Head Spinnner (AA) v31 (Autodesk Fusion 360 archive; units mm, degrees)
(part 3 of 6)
sketch "Switch Housing Clearance" plane through (0, 0, -2.54) normal (0, 0, -1) x axis (1, 0, 0)
  line L1 (-21.6642, -66.6778) -> (23.0262, -66.6778)
  line L2 (-30.1868, -67.591) -> (-21.6642, -66.6778)
  line L3 (-30.1868, -39.2217) -> (-30.1868, -67.591)
  line L4 (-21.6642, -40.1348) -> (-30.1868, -39.2217)
  line L5 (23.0262, -40.1348) -> (-21.6642, -40.1348)
  line L6 (23.0262, -66.6778) -> (23.0262, -40.1348)
  line L7 (-11.2776, 70.5993) -> (-11.2776, 56.4007)
  line L8 (10.5219, 71.0121) -> (-10.522, 71.0121)
  line L9 (11.2776, 56.4007) -> (11.2776, 70.5993)
  line L10 (-10.522, 55.988) -> (10.5219, 55.988)
  line L11 (-11.2776, 55.988) -> (-10.522, 55.988)
  line L12 (-11.2776, 55.988) -> (-11.2776, 56.4007)
  line L13 (11.2776, 71.0121) -> (11.2776, 70.5993)
  line L14 (11.2776, 71.0121) -> (10.5219, 71.0121)
  line L15 (11.2776, 55.988) -> (-11.2776, 55.988)
  line L16 (11.2776, 71.0121) -> (11.2776, 55.988)
  line L17 (-11.2776, 71.0121) -> (11.2776, 71.0121)
  line L18 (-11.2776, 55.988) -> (-11.2776, 71.0121)
  line L19 (-11.5316, 71.2661) -> (11.5316, 71.2661)
  line L20 (-11.5316, 55.734) -> (-11.5316, 71.2661)
  line L21 (11.5316, 55.734) -> (-11.5316, 55.734)
  line L22 (11.5316, 71.2661) -> (11.5316, 55.734)
  circle C1 centre (0, -84.1375) radius 3.328
  circle C2 centre (82.028, 18.7224) radius 3.328
  circle C3 centre (-36.5059, 75.8053) radius 3.328
  circle C4 centre (-65.7813, -52.4589) radius 3.328
  circle C5 centre (0, 0) radius 88.9
  circle C6 centre (-82.028, 18.7224) radius 3.328
  circle C7 centre (36.5059, 75.8053) radius 3.328
  circle C8 centre (65.7813, -52.4589) radius 3.328
  point P23 (-10.522, 55.988)
  point P24 (-10.522, 55.988)
  point P16 (-11.2776, 56.4007)
  point P25 (-11.2776, 56.4007)
  point P20 (11.2776, 70.5993)
  point P27 (11.2776, 70.5993)
  point P19 (10.5219, 71.0121)
  point P28 (10.5219, 71.0121)
  coincident P23 P24
  parallel L10 L11
  coincident P16 P25
  vertical L12
  coincident P20 P27
  parallel L9 L13
  coincident P19 P28
  perpendicular L13 L14
  horizontal L15
  vertical L16
  horizontal L17
  vertical L18
extrude "Extrude20" cut sketch "Switch Housing Clearance" profile of L20 L19 L21 L22 against normal blind 5.715
offset_faces "OffsetFaces3" distance 0.0318
extrude "Extrude30" add of existing geometry blind 0.2794
extrude "Extrude31" add of existing geometry blind 0.3048
fillet "Fillet4" radius 0.635
chamfer "Chamfer6" distance 1.27
sketch "Battery Cover Profile" plane through (0, 0, -2.54) normal (0, 0, -1) x axis (1, 0, 0)
  line L1 (11.2268, 71.2661) -> (-11.2522, 71.2661)
  line L2 (-11.2522, 55.734) -> (11.2268, 55.734)
  line L3 (-21.6642, -66.6778) -> (23.0262, -66.6778)
  line L4 (-30.1868, -67.591) -> (-21.6642, -66.6778)
  line L5 (-30.1868, -39.2217) -> (-30.1868, -67.591)
  line L6 (-21.6642, -40.1348) -> (-30.1868, -39.2217)
  line L7 (23.0262, -40.1348) -> (-21.6642, -40.1348)
  line L8 (23.0262, -66.6778) -> (23.0262, -40.1348)
  line L9 (-21.5285, -69.2178) -> (25.5662, -69.2178)
  line L10 (-32.7268, -70.4176) -> (-21.5285, -69.2178)
  line L11 (-32.7268, -36.395) -> (-32.7268, -70.4176)
  line L12 (-21.5285, -37.5948) -> (-32.7268, -36.395)
  line L13 (25.5662, -37.5948) -> (-21.5285, -37.5948)
  line L14 (25.5662, -69.2178) -> (25.5662, -37.5948)
  line L15 (-39.0768, -47.6913) -> (-32.7268, -47.6913)
  line L16 (-39.0768, -59.1213) -> (-39.0768, -47.6913)
  line L17 (-32.7268, -59.1213) -> (-39.0768, -59.1213)
  line L18 (-32.7268, -53.4063) -> (-39.0768, -53.4063)
  line L19 (25.5662, -53.4063) -> (-32.7268, -53.4063)
  line L20 (-3.5803, -33.02) -> (-3.5803, -53.4063)
  line L21 (31.9162, -47.6913) -> (25.5662, -47.6913)
  line L22 (25.5662, -59.1213) -> (31.9162, -59.1213)
  line L23 (11.2268, 55.734) -> (11.2268, 71.2661)
  line L24 (-11.2522, 71.2661) -> (-11.2522, 55.734)
  circle C1 centre (0, -84.1375) radius 3.328
  circle C2 centre (82.028, 18.7224) radius 3.328
  circle C3 centre (-36.5059, 75.8053) radius 3.328
  circle C4 centre (-65.7813, -52.4589) radius 3.328
  circle C5 centre (0, 0) radius 88.9
  circle C6 centre (-82.028, 18.7224) radius 3.328
  circle C7 centre (36.5059, 75.8053) radius 3.328
  circle C8 centre (65.7813, -52.4589) radius 3.328
  arc A1 centre (-39.0768, -53.4063) radius 5.715 clockwise from (-39.0768, -59.1213) to (-39.0768, -47.6913)
  arc A2 centre (31.9162, -53.4063) radius 5.715 clockwise from (31.9162, -47.6913) to (31.9162, -59.1213)
  point P26 (-32.7268, -47.6913)
  point P29 (-32.7268, -59.1213)
  point P31 (-39.0768, -53.4063)
  point P32 (-32.7268, -53.4063)
  point P33 (25.5662, -53.4063)
  point P34 (-3.5803, -53.4063)
  point P36 (25.5662, -47.6913)
  point P27 (-39.0768, -47.6913)
  point P37 (31.9162, -47.6913)
  point P28 (-39.0768, -59.1213)
  point P38 (31.9162, -59.1213)
  point P39 (25.5662, -59.1213)
  coincident L11 P26
  perpendicular L11 L15
  perpendicular L15 L16
  coincident L11 P29
  horizontal L17
  midpoint L16 P31
  midpoint L11 P32
  horizontal L18
  tangent L17 A1
  midpoint L14 P33
  midpoint L19 P34
  perpendicular L13 L20
  symmetric P26 L20 P36
  symmetric P27 L20 P37
  symmetric P28 L20 P38
  symmetric P29 L20 P39
  symmetric A1 L20 A2
  dimension "d240" = -2.54
  dimension "d241" distance P27 P28 = 11.43
  dimension "d242" distance P26 P27 = 6.35
extrude "Extrude23" cut sketch "Battery Cover Profile" profile of L3 L4 L5 L6 L7 L8 L14 L12 L10 L11 L13 L9 L15 L17 A1 L21 L22 A2 against normal blind 1.905
extrude "Extrude24" sketch "Battery Cover Profile" profile of L14 L11 L15 L17 A1 L21 L22 A2 blind -5.08
fillet "Fillet5" radius 1.27
sketch "Battery Cover Clearance" plane through (0, 0, -0.635) normal (0, 0, -1) x axis (1, 0, 0)
  line L1 (-32.7268, -46.4213) -> (-32.7268, -37.8084)
  line L2 (-39.0768, -47.6913) -> (-33.9968, -47.6913)
  line L3 (-33.9968, -59.1213) -> (-39.0768, -59.1213)
  line L4 (-32.7268, -69.0043) -> (-32.7268, -60.3913)
  line L5 (-21.596, -69.2251) -> (-31.3215, -70.2671)
  line L6 (24.2962, -69.2178) -> (-21.4607, -69.2178)
  line L7 (25.5662, -60.3913) -> (25.5662, -67.9478)
  line L8 (31.9162, -59.1213) -> (26.8362, -59.1213)
  line L9 (26.8362, -47.6913) -> (31.9162, -47.6913)
  line L10 (25.5662, -38.8648) -> (25.5662, -46.4213)
  line L11 (-21.4607, -37.5948) -> (24.2962, -37.5948)
  line L12 (-31.3215, -36.5456) -> (-21.596, -37.5876)
  line L13 (23.0262, -40.1348) -> (-21.6642, -40.1348)
  line L14 (23.0262, -66.6778) -> (23.0262, -40.1348)
  line L15 (-21.6642, -66.6778) -> (23.0262, -66.6778)
  line L16 (-30.1868, -67.591) -> (-21.6642, -66.6778)
  line L17 (-30.1868, -39.2217) -> (-30.1868, -67.591)
  line L18 (-21.6642, -40.1348) -> (-30.1868, -39.2217)
  line L19 (26.8362, -48.0723) -> (31.9162, -48.0723)
  line L20 (31.9162, -58.7403) -> (26.8362, -58.7403)
  line L21 (25.1852, -60.3913) -> (25.1852, -67.9478)
  line L22 (24.2962, -68.8368) -> (-21.4607, -68.8368)
  line L23 (-21.6366, -68.8462) -> (-31.3621, -69.8882)
  line L24 (-32.3458, -69.0043) -> (-32.3458, -60.3913)
  line L25 (-33.9968, -58.7403) -> (-39.0768, -58.7403)
  line L26 (-39.0768, -48.0723) -> (-33.9968, -48.0723)
  line L27 (-32.3458, -46.4213) -> (-32.3458, -37.8084)
  line L28 (-31.3621, -36.9244) -> (-21.6366, -37.9664)
  line L29 (-21.4607, -37.9758) -> (24.2962, -37.9758)
  line L30 (25.1852, -38.8648) -> (25.1852, -46.4213)
  arc A1 centre (-31.4568, -37.8084) radius 1.27 clockwise from (-32.7268, -37.8084) to (-31.3215, -36.5456)
  arc A2 centre (-33.9968, -46.4213) radius 1.27 clockwise from (-32.7268, -46.4213) to (-33.9968, -47.6913)
  arc A3 centre (-39.0768, -53.4063) radius 5.715 clockwise from (-39.0768, -59.1213) to (-39.0768, -47.6913)
  arc A4 centre (-33.9968, -60.3913) radius 1.27 clockwise from (-33.9968, -59.1213) to (-32.7268, -60.3913)
  arc A5 centre (-31.4568, -69.0043) radius 1.27 clockwise from (-31.3215, -70.2671) to (-32.7268, -69.0043)
  arc A6 centre (-21.4607, -70.4878) radius 1.27 clockwise from (-21.596, -69.2251) to (-21.4607, -69.2178)
  arc A7 centre (24.2962, -67.9478) radius 1.27 clockwise from (25.5662, -67.9478) to (24.2962, -69.2178)
  arc A8 centre (26.8362, -60.3913) radius 1.27 clockwise from (25.5662, -60.3913) to (26.8362, -59.1213)
  arc A9 centre (31.9162, -53.4063) radius 5.715 clockwise from (31.9162, -47.6913) to (31.9162, -59.1213)
  arc A10 centre (26.8362, -46.4213) radius 1.27 clockwise from (26.8362, -47.6913) to (25.5662, -46.4213)
  arc A11 centre (24.2962, -38.8648) radius 1.27 clockwise from (24.2962, -37.5948) to (25.5662, -38.8648)
  arc A12 centre (-21.4607, -36.3248) radius 1.27 clockwise from (-21.4607, -37.5948) to (-21.596, -37.5876)
  arc A13 centre (26.8362, -46.4213) radius 1.651 clockwise from (26.8362, -48.0723) to (25.1852, -46.4213)
  arc A14 centre (31.9162, -53.4063) radius 5.334 clockwise from (31.9162, -48.0723) to (31.9162, -58.7403)
  arc A15 centre (26.8362, -60.3913) radius 1.651 clockwise from (25.1852, -60.3913) to (26.8362, -58.7403)
  arc A16 centre (24.2962, -67.9478) radius 0.889 clockwise from (25.1852, -67.9478) to (24.2962, -68.8368)
  arc A17 centre (-21.4607, -70.4878) radius 1.651 clockwise from (-21.6366, -68.8462) to (-21.4607, -68.8368)
  arc A18 centre (-31.4568, -69.0043) radius 0.889 clockwise from (-31.3621, -69.8882) to (-32.3458, -69.0043)
  arc A19 centre (-33.9968, -60.3913) radius 1.651 clockwise from (-33.9968, -58.7403) to (-32.3458, -60.3913)
  arc A20 centre (-39.0768, -53.4063) radius 5.334 clockwise from (-39.0768, -58.7403) to (-39.0768, -48.0723)
  arc A21 centre (-33.9968, -46.4213) radius 1.651 clockwise from (-32.3458, -46.4213) to (-33.9968, -48.0723)
  arc A22 centre (-31.4568, -37.8084) radius 0.889 clockwise from (-32.3458, -37.8084) to (-31.3621, -36.9244)
  arc A23 centre (-21.4607, -36.3248) radius 1.651 clockwise from (-21.4607, -37.9758) to (-21.6366, -37.9664)
  arc A24 centre (24.2962, -38.8648) radius 0.889 clockwise from (24.2962, -37.9758) to (25.1852, -38.8648)
  dimension "d430" = -0.381 (= "-clearance * 1.5")
sketch "Motor Control Text" plane through (0, 0, -2.54) normal (0, 0, -1) x axis (1, 0, 0)
  line L1 (11.2268, 71.2661) -> (-11.2522, 71.2661)
  line L2 (11.2268, 55.734) -> (11.2268, 71.2661)
  line L3 (-11.2522, 55.734) -> (11.2268, 55.734)
  line L4 (-11.2522, 71.2661) -> (-11.2522, 55.734)
  line L5 (24.2962, -37.5948) -> (-21.4607, -37.5948)
  line L6 (25.5662, -46.4213) -> (25.5662, -38.8648)
  line L7 (31.9162, -47.6913) -> (26.8362, -47.6913)
  line L8 (26.8362, -59.1213) -> (31.9162, -59.1213)
  line L9 (25.5662, -67.9478) -> (25.5662, -60.3913)
  line L10 (-21.4607, -69.2178) -> (24.2962, -69.2178)
  line L11 (-31.3215, -70.2671) -> (-21.596, -69.2251)
  line L12 (-32.7268, -60.3913) -> (-32.7268, -69.0043)
  line L13 (-39.0768, -59.1213) -> (-33.9968, -59.1213)
  line L14 (-33.9968, -47.6913) -> (-39.0768, -47.6913)
  line L15 (-32.7268, -37.8084) -> (-32.7268, -46.4213)
  line L16 (-21.596, -37.5876) -> (-31.3215, -36.5456)
  curve K1
  curve K2
  curve K3
  curve K4
  curve K5
  curve K6
  curve K7
  curve K8
  line L17 (20.545, 64.2667) -> (20.545, 63.1491)
  line L18 (23.9552, 60.6091) -> (23.389, 60.6091)
  line L19 (22.8228, 60.6091) -> (20.545, 60.6091)
  line L20 (20.545, 63.1491) -> (20.545, 60.6091)
  line L21 (24.6329, 59.4026) -> (23.9552, 60.6091)
  line L22 (22.8228, 60.6091) -> (22.1452, 59.4026)
  line L23 (23.389, 59.4026) -> (23.389, 60.6091)
  line L24 (23.389, 61.6172) -> (22.8228, 60.6091)
  line L25 (23.9552, 60.6091) -> (23.389, 61.6172)
  line L26 (23.389, 60.6091) -> (22.8228, 60.6091)
  line L27 (23.9979, 59.4026) -> (24.6329, 59.4026)
  line L28 (22.1452, 59.4026) -> (22.7802, 59.4026)
  line L29 (22.7802, 59.4026) -> (23.9979, 59.4026)
  line L30 (-0.0127, 48.26) -> (-0.0127, 55.734)
  line L31 (-20.5704, 64.2667) -> (-20.5704, 63.1491)
  line L32 (-24.6583, 59.4026) -> (-23.9806, 60.6091)
  line L33 (-24.0233, 59.4026) -> (-24.6583, 59.4026)
  line L34 (-22.1706, 59.4026) -> (-22.8056, 59.4026)
  line L35 (-22.8482, 60.6091) -> (-22.1706, 59.4026)
  line L36 (-23.4144, 61.6172) -> (-22.8482, 60.6091)
  line L37 (-23.9806, 60.6091) -> (-23.4144, 61.6172)
  line L38 (-17.7927, 76.7271) -> (17.7673, 76.7271)
  line L39 (17.7546, 63.5) -> (-17.78, 63.5)
  line L40 (30.2768, 63.5) -> (-30.3022, 63.5)
  line L41 (-0.0127, 55.734) -> (-0.0127, 63.5)
  line L42 (17.7673, 52.559) -> (-17.7927, 52.559)
  line L43 (-17.7927, 76.8541) -> (17.7673, 76.8541)
  line L44 (17.7673, 52.432) -> (-17.7927, 52.432)
  circle C1 centre (65.7813, -52.4589) radius 3.328
  circle C2 centre (36.5059, 75.8053) radius 3.328
  circle C3 centre (-82.028, 18.7224) radius 3.328
  circle C4 centre (0, 0) radius 88.9
  circle C5 centre (-65.7813, -52.4589) radius 3.328
  circle C6 centre (-36.5059, 75.8053) radius 3.328
  circle C7 centre (82.028, 18.7224) radius 3.328
  circle C8 centre (0, -84.1375) radius 3.328
  arc A1 centre (-21.4607, -36.3248) radius 1.27 clockwise from (-21.4607, -37.5948) to (-21.596, -37.5876)
  arc A2 centre (24.2962, -38.8648) radius 1.27 clockwise from (24.2962, -37.5948) to (25.5662, -38.8648)
  arc A3 centre (26.8362, -46.4213) radius 1.27 clockwise from (26.8362, -47.6913) to (25.5662, -46.4213)
  arc A4 centre (31.9162, -53.4063) radius 5.715 clockwise from (31.9162, -47.6913) to (31.9162, -59.1213)
  arc A5 centre (26.8362, -60.3913) radius 1.27 clockwise from (25.5662, -60.3913) to (26.8362, -59.1213)
  arc A6 centre (24.2962, -67.9478) radius 1.27 clockwise from (25.5662, -67.9478) to (24.2962, -69.2178)
  arc A7 centre (-21.4607, -70.4878) radius 1.27 clockwise from (-21.596, -69.2251) to (-21.4607, -69.2178)
  arc A8 centre (-31.4568, -69.0043) radius 1.27 clockwise from (-31.3215, -70.2671) to (-32.7268, -69.0043)
  arc A9 centre (-33.9968, -60.3913) radius 1.27 clockwise from (-33.9968, -59.1213) to (-32.7268, -60.3913)
  arc A10 centre (-39.0768, -53.4063) radius 5.715 clockwise from (-39.0768, -59.1213) to (-39.0768, -47.6913)
  arc A11 centre (-33.9968, -46.4213) radius 1.27 clockwise from (-32.7268, -46.4213) to (-33.9968, -47.6913)
  arc A12 centre (-31.4568, -37.8084) radius 1.27 clockwise from (-32.7268, -37.8084) to (-31.3215, -36.5456)
  arc A13 centre (20.545, 60.6091) radius 2.54 clockwise from (22.7802, 59.4026) to (20.545, 63.1491)
  arc A14 centre (20.545, 60.6091) radius 3.6576 clockwise from (23.9979, 59.4026) to (20.545, 64.2667)
  arc A15 centre (-20.5704, 60.6091) radius 3.6576 clockwise from (-20.5704, 64.2667) to (-24.0233, 59.4026)
  arc A16 centre (-20.5704, 60.6091) radius 2.54 clockwise from (-20.5704, 63.1491) to (-22.8056, 59.4026)
  arc A17 centre (-17.7927, 64.643) radius 12.0841 clockwise from (-17.7927, 52.559) to (-17.7927, 76.7271)
  arc A18 centre (17.7673, 64.643) radius 12.0841 clockwise from (17.7673, 76.7271) to (17.7673, 52.559)
  arc A19 centre (17.7673, 64.643) radius 12.2111 clockwise from (17.7673, 76.8541) to (17.7673, 52.432)
  arc A20 centre (-17.7927, 64.643) radius 12.2111 clockwise from (-17.7927, 52.432) to (-17.7927, 76.8541)
  point P12 (11.2268, 55.734)
  point P10 (-11.2522, 71.2661)
  point P50 (20.545, 60.6091)
  point P52 (20.545, 60.6091)
  point P62 (22.7802, 59.4026)
  point P60 (23.389, 59.4026)
  point P51 (20.545, 60.6091)
  point P64 (23.389, 59.4026)
  point P65 (-0.0127, 55.734)
  point P53 (20.545, 64.2667)
  point P68 (-20.5704, 64.2667)
  point P54 (23.9552, 60.6091)
  point P73 (-23.9806, 60.6091)
  point P55 (22.8228, 60.6091)
  point P76 (-22.8482, 60.6091)
  point P56 (20.545, 63.1491)
  point P71 (-20.5704, 63.1491)
  point P57 (24.6329, 59.4026)
  point P74 (-24.6583, 59.4026)
  point P58 (22.1452, 59.4026)
  point P75 (-22.1706, 59.4026)
  point P61 (23.389, 61.6172)
  point P77 (-23.4144, 61.6172)
  point P72 (-22.8056, 59.4026)
  point P63 (23.9979, 59.4026)
  point P69 (-24.0233, 59.4026)
  point P84 (-0.0127, 63.5)
  point P85 (-30.3022, 63.5)
  point P86 (30.2768, 63.5)
  point P87 (-0.0127, 63.5)
  point P88 (-0.0127, 63.5)
  point P13 (-11.2522, 55.734)
  point P89 (-0.0127, 52.559)
  point P59 (23.389, 60.6091)
  point P80 (17.7673, 76.7271)
  point P81 (-17.7927, 76.7271)
  coincident P12
  coincident P10
  equal K1 K5
  horizontal K1
  horizontal K5
  coincident P50 P52
  horizontal L18
  horizontal L19
  horizontal L27
  vertical L23
  horizontal L26
  coincident P62 L27
  coincident P60 L29
  coincident P50 P51
  equal L27 L28
  equal L21 L22
  equal L24 L25
  collinear L21 L25
  collinear L22 L24
  midpoint L29 P64
  coincident P60 P64
  midpoint L3 P65
  perpendicular L3 L30
  symmetric P53 L30 P68
  symmetric P54 L30 P73
  symmetric P55 L30 P76
  symmetric P56 L30 P71
  symmetric A13 L30 A16
  symmetric A14 L30 A15
  symmetric P57 L30 P74
  symmetric P58 L30 P75
  symmetric P61 L30 P77
  symmetric P62 L30 P72
  symmetric P63 L30 P69
  perpendicular L2 L39
  midpoint L39 P84
  midpoint K8 P85
  midpoint K2 P86
  midpoint L40 P87
  coincident P84 P87
  coincident P87 P88
  horizontal L40
  coincident P13
  midpoint L42 P89
  coincident L30 P89
  tangent L42 A18
  tangent L38 A18
  tangent L38 A17
  tangent L42 A17
  dimension "d478" angle L17 L18 = 90
  dimension "d479" distance A13 A14 = 1.1176
  dimension "d480" distance P57 P61 = 2.54
  dimension "d481" distance P59 P60 = 1.2065
  dimension "d482" distance P57 P63 = 0.635
  dimension "d483" radius A13 = 2.54
  dimension "d484" distance L1 L38 = 5.461
  dimension "d485" distance L3 L42 = 3.175
  dimension "d486" distance P80 P81 = 35.56
  dimension "d487" = 0.127
  dimension "d472" Text1-Height = 3.81
  dimension "d473" Text2-Height = 3.81
  dimension "d474" distance = 19.05
extrude "Extrude34" cut sketch "Motor Control Text" profile of L17 A13 A14 L21 L22 L24 L25 L27 L28 A15 A16 L31 L32 L33 L34 L35 L36 L37 L38 L42 A17 A18 L44 A20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 against normal blind 0.889
extrude "Extrude26" new body sketch "Battery Cover Clearance" profile of L13 L14 L15 L16 L17 L18 L20 A13 L29 L19 L21 L30 A16 A14 A15 L22 A17 L23 A18 A24 L24 A19 L26 L25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 along normal blind 1.8415
extrude "Extrude32" cut of existing geometry blind -0.127
sketch "Battery Cover Holes" plane through (0, 0, -2.3495) normal (0, 0, -1) x axis (1, 0, 0)
  line L1 (31.9162, -58.6133) -> (26.8362, -58.6133)
  line L2 (26.8362, -48.1993) -> (31.9162, -48.1993)
  line L3 (25.0582, -38.8648) -> (25.0582, -46.4213)
  line L4 (-21.4607, -38.1028) -> (24.2962, -38.1028)
  line L5 (-31.3756, -37.0507) -> (-21.6501, -38.0927)
  line L6 (-32.2188, -46.4213) -> (-32.2188, -37.8084)
  line L7 (-39.0768, -48.1993) -> (-33.9968, -48.1993)
  line L8 (-33.9968, -58.6133) -> (-39.0768, -58.6133)
  line L9 (-32.2188, -69.0043) -> (-32.2188, -60.3913)
  line L10 (-21.6501, -68.7199) -> (-31.3756, -69.762)
  line L11 (24.2962, -68.7098) -> (-21.4607, -68.7098)
  line L12 (25.0582, -60.3913) -> (25.0582, -67.9478)
  line L13 (31.9162, -58.7403) -> (26.8362, -58.7403)
  line L14 (26.8362, -48.0723) -> (31.9162, -48.0723)
  line L15 (25.1852, -38.8648) -> (25.1852, -46.4213)
  line L16 (-21.4607, -37.9758) -> (24.2962, -37.9758)
  line L17 (-31.3621, -36.9244) -> (-21.6366, -37.9664)
  line L18 (-32.3458, -46.4213) -> (-32.3458, -37.8084)
  line L19 (-39.0768, -48.0723) -> (-33.9968, -48.0723)
  line L20 (-33.9968, -58.7403) -> (-39.0768, -58.7403)
  line L21 (-32.3458, -69.0043) -> (-32.3458, -60.3913)
  line L22 (-21.6366, -68.8462) -> (-31.3621, -69.8882)
  line L23 (24.2962, -68.8368) -> (-21.4607, -68.8368)
  line L24 (25.1852, -60.3913) -> (25.1852, -67.9478)
  circle C1 centre (-39.0768, -53.4063) radius 1.5
  circle C2 centre (31.9162, -53.4063) radius 1.5
  arc A1 centre (31.9162, -53.4063) radius 5.207 clockwise from (31.9162, -48.1993) to (31.9162, -58.6133)
  arc A2 centre (26.8362, -46.4213) radius 1.778 clockwise from (26.8362, -48.1993) to (25.0582, -46.4213)
  arc A3 centre (24.2962, -38.8648) radius 0.762 clockwise from (24.2962, -38.1028) to (25.0582, -38.8648)
  arc A4 centre (-21.4607, -36.3248) radius 1.778 clockwise from (-21.4607, -38.1028) to (-21.6501, -38.0927)
  arc A5 centre (-31.4568, -37.8084) radius 0.762 clockwise from (-32.2188, -37.8084) to (-31.3756, -37.0507)
  arc A6 centre (-33.9968, -46.4213) radius 1.778 clockwise from (-32.2188, -46.4213) to (-33.9968, -48.1993)
  arc A7 centre (-39.0768, -53.4063) radius 5.207 clockwise from (-39.0768, -58.6133) to (-39.0768, -48.1993)
  arc A8 centre (-33.9968, -60.3913) radius 1.778 clockwise from (-33.9968, -58.6133) to (-32.2188, -60.3913)
  arc A9 centre (-31.4568, -69.0043) radius 0.762 clockwise from (-31.3756, -69.762) to (-32.2188, -69.0043)
  arc A10 centre (-21.4607, -70.4878) radius 1.778 clockwise from (-21.6501, -68.7199) to (-21.4607, -68.7098)
  arc A11 centre (24.2962, -67.9478) radius 0.762 clockwise from (25.0582, -67.9478) to (24.2962, -68.7098)
  arc A12 centre (26.8362, -60.3913) radius 1.778 clockwise from (25.0582, -60.3913) to (26.8362, -58.6133)
  arc A13 centre (31.9162, -53.4063) radius 5.334 clockwise from (31.9162, -48.0723) to (31.9162, -58.7403)
  arc A14 centre (26.8362, -46.4213) radius 1.651 clockwise from (26.8362, -48.0723) to (25.1852, -46.4213)
  arc A15 centre (24.2962, -38.8648) radius 0.889 clockwise from (24.2962, -37.9758) to (25.1852, -38.8648)
  arc A16 centre (-21.4607, -36.3248) radius 1.651 clockwise from (-21.4607, -37.9758) to (-21.6366, -37.9664)
  arc A17 centre (-31.4568, -37.8084) radius 0.889 clockwise from (-32.3458, -37.8084) to (-31.3621, -36.9244)
  arc A18 centre (-33.9968, -46.4213) radius 1.651 clockwise from (-32.3458, -46.4213) to (-33.9968, -48.0723)
  arc A19 centre (-39.0768, -53.4063) radius 5.334 clockwise from (-39.0768, -58.7403) to (-39.0768, -48.0723)
  arc A20 centre (-33.9968, -60.3913) radius 1.651 clockwise from (-33.9968, -58.7403) to (-32.3458, -60.3913)
  arc A21 centre (-31.4568, -69.0043) radius 0.889 clockwise from (-31.3621, -69.8882) to (-32.3458, -69.0043)
  arc A22 centre (-21.4607, -70.4878) radius 1.651 clockwise from (-21.6366, -68.8462) to (-21.4607, -68.8368)
  arc A23 centre (24.2962, -67.9478) radius 0.889 clockwise from (25.1852, -67.9478) to (24.2962, -68.8368)
  arc A24 centre (26.8362, -60.3913) radius 1.651 clockwise from (25.1852, -60.3913) to (26.8362, -58.7403)
  point P3 (31.9162, -53.4063)
  point P7 (31.9162, -53.4063)
  point P2 (-39.0768, -53.4063)
  point P25 (-39.0768, -53.4063)
  equal C1 C2
  coincident P3 P7
  coincident P2 P25
  dimension "d255" diameter C1 = 3
extrude "Extrude27" cut sketch "Battery Cover Holes" profile of C1 C2 against normal blind 22.86
sketch "Battery Cover Holes Clearance" plane through (0, 0, -2.3495) normal (0, 0, -1) x axis (1, 0, 0)
  line L1 (31.9162, -58.6133) -> (26.8362, -58.6133)
  line L2 (26.8362, -48.1993) -> (31.9162, -48.1993)
  line L3 (25.0582, -38.8648) -> (25.0582, -46.4213)
  line L4 (-21.4607, -38.1028) -> (24.2962, -38.1028)
  line L5 (-31.3756, -37.0507) -> (-21.6501, -38.0927)
  line L6 (-32.2188, -46.4213) -> (-32.2188, -37.8084)
  line L7 (-39.0768, -48.1993) -> (-33.9968, -48.1993)
  line L8 (-33.9968, -58.6133) -> (-39.0768, -58.6133)
  line L9 (-32.2188, -69.0043) -> (-32.2188, -60.3913)
  line L10 (-21.6501, -68.7199) -> (-31.3756, -69.762)
  line L11 (24.2962, -68.7098) -> (-21.4607, -68.7098)
  line L12 (25.0582, -60.3913) -> (25.0582, -67.9478)
  line L13 (31.9162, -58.7403) -> (26.8362, -58.7403)
  line L14 (26.8362, -48.0723) -> (31.9162, -48.0723)
  line L15 (25.1852, -38.8648) -> (25.1852, -46.4213)
  line L16 (-21.4607, -37.9758) -> (24.2962, -37.9758)
  line L17 (-31.3621, -36.9244) -> (-21.6366, -37.9664)
  line L18 (-32.3458, -46.4213) -> (-32.3458, -37.8084)
  line L19 (-39.0768, -48.0723) -> (-33.9968, -48.0723)
  line L20 (-33.9968, -58.7403) -> (-39.0768, -58.7403)
  line L21 (-32.3458, -69.0043) -> (-32.3458, -60.3913)
  line L22 (-21.6366, -68.8462) -> (-31.3621, -69.8882)
  line L23 (24.2962, -68.8368) -> (-21.4607, -68.8368)
  line L24 (25.1852, -60.3913) -> (25.1852, -67.9478)
  circle C1 centre (-39.0768, -53.4063) radius 1.5
  circle C2 centre (31.9162, -53.4063) radius 1.5
  circle C3 centre (31.9162, -53.4063) radius 1.754
  circle C4 centre (-39.0768, -53.4063) radius 1.754
  arc A1 centre (31.9162, -53.4063) radius 5.207 clockwise from (31.9162, -48.1993) to (31.9162, -58.6133)
  arc A2 centre (26.8362, -46.4213) radius 1.778 clockwise from (26.8362, -48.1993) to (25.0582, -46.4213)
  arc A3 centre (24.2962, -38.8648) radius 0.762 clockwise from (24.2962, -38.1028) to (25.0582, -38.8648)
  arc A4 centre (-21.4607, -36.3248) radius 1.778 clockwise from (-21.4607, -38.1028) to (-21.6501, -38.0927)
  arc A5 centre (-31.4568, -37.8084) radius 0.762 clockwise from (-32.2188, -37.8084) to (-31.3756, -37.0507)
  arc A6 centre (-33.9968, -46.4213) radius 1.778 clockwise from (-32.2188, -46.4213) to (-33.9968, -48.1993)
  arc A7 centre (-39.0768, -53.4063) radius 5.207 clockwise from (-39.0768, -58.6133) to (-39.0768, -48.1993)
  arc A8 centre (-33.9968, -60.3913) radius 1.778 clockwise from (-33.9968, -58.6133) to (-32.2188, -60.3913)
  arc A9 centre (-31.4568, -69.0043) radius 0.762 clockwise from (-31.3756, -69.762) to (-32.2188, -69.0043)
  arc A10 centre (-21.4607, -70.4878) radius 1.778 clockwise from (-21.6501, -68.7199) to (-21.4607, -68.7098)
  arc A11 centre (24.2962, -67.9478) radius 0.762 clockwise from (25.0582, -67.9478) to (24.2962, -68.7098)
  arc A12 centre (26.8362, -60.3913) radius 1.778 clockwise from (25.0582, -60.3913) to (26.8362, -58.6133)
  circle C5 centre (-39.0768, -53.4063) radius 1.5
  circle C6 centre (31.9162, -53.4063) radius 1.5
  arc A13 centre (31.9162, -53.4063) radius 5.334 clockwise from (31.9162, -48.0723) to (31.9162, -58.7403)
  arc A14 centre (26.8362, -46.4213) radius 1.651 clockwise from (26.8362, -48.0723) to (25.1852, -46.4213)
  arc A15 centre (24.2962, -38.8648) radius 0.889 clockwise from (24.2962, -37.9758) to (25.1852, -38.8648)
  arc A16 centre (-21.4607, -36.3248) radius 1.651 clockwise from (-21.4607, -37.9758) to (-21.6366, -37.9664)
  arc A17 centre (-31.4568, -37.8084) radius 0.889 clockwise from (-32.3458, -37.8084) to (-31.3621, -36.9244)
  arc A18 centre (-33.9968, -46.4213) radius 1.651 clockwise from (-32.3458, -46.4213) to (-33.9968, -48.0723)
  arc A19 centre (-39.0768, -53.4063) radius 5.334 clockwise from (-39.0768, -58.7403) to (-39.0768, -48.0723)
  arc A20 centre (-33.9968, -60.3913) radius 1.651 clockwise from (-33.9968, -58.7403) to (-32.3458, -60.3913)
  arc A21 centre (-31.4568, -69.0043) radius 0.889 clockwise from (-31.3621, -69.8882) to (-32.3458, -69.0043)
  arc A22 centre (-21.4607, -70.4878) radius 1.651 clockwise from (-21.6366, -68.8462) to (-21.4607, -68.8368)
  arc A23 centre (24.2962, -67.9478) radius 0.889 clockwise from (25.1852, -67.9478) to (24.2962, -68.8368)
  arc A24 centre (26.8362, -60.3913) radius 1.651 clockwise from (25.1852, -60.3913) to (26.8362, -58.7403)
  dimension "d258" = 0.254 (= "clearance")
  dimension "d260" = 0.254 (= "clearance")
extrude "Extrude28" cut sketch "Battery Cover Holes Clearance" profile of C1 C2 C3 C4 against normal blind 17.78
component_from_bodies "Body->Comp1"
joint "Assemble1" alignAngle 0 alignOffsetX 0 alignOffsetY 0 alignOffsetZ 0 SlideMaximum 0
chamfer "Chamfer7" distance 0.3175
chamfer "Chamfer1" distance 1.524
sketch "Driven Gear Cover -> Drive Cut Out" plane through (0, 0, 33.02) normal (0, 0, -1) x axis (1, 0, 0)
  line L1 (4.7625, -17.78) -> (-4.7625, -17.78)
  line L2 (10.7345, -23.0202) -> (0, 0)
  line L3 (19.05, 0) -> (0, 0)
  line L4 (10.7345, 23.0202) -> (0, 0)
  line L5 (19.05, 0) -> (0, 0)
  line L6 (10.4547, -22.4202) -> (10.4547, 22.4202)
  curve K1 (55.9949, 5.6104) -> (55.4891, 7.1671)
  curve K2 (57.3848, 8.9033) -> (55.4891, 7.1671)
  curve K3 (56.952, 9.8754) -> (54.3933, 9.6284)
  curve K4 (54.3933, 9.6284) -> (53.5748, 11.046)
  curve K5 (55.0681, 13.1384) -> (53.5748, 11.046)
  curve K6 (54.4426, 13.9993) -> (51.9912, 13.2257)
  curve K7 (51.9912, 13.2257) -> (50.8959, 14.4421)
  curve K8 (51.9215, 16.7993) -> (50.8959, 14.4421)
  curve K9 (51.1307, 17.5113) -> (48.8937, 16.2449)
  curve K10 (48.8937, 16.2449) -> (47.5694, 17.2071)
  curve K11 (48.0826, 19.7259) -> (47.5694, 17.2071)
  curve K12 (47.161, 20.258) -> (45.2362, 18.5542)
  curve K13 (45.2362, 18.5542) -> (43.7408, 19.22)
  curve K14 (43.719, 21.7904) -> (43.7408, 19.22)
  curve K15 (42.707, 22.1193) -> (41.1784, 20.0525)
  curve K16 (41.1784, 20.0525) -> (39.5773, 20.3928)
  curve K17 (39.0216, 22.9026) -> (39.5773, 20.3928)
  curve K18 (37.9633, 23.0139) -> (36.8979, 20.6745)
  curve K19 (36.8979, 20.6745) -> (35.261, 20.6745)
  curve K20 (34.1956, 23.0139) -> (35.261, 20.6745)
  curve K21 (33.1373, 22.9026) -> (32.5815, 20.3928)
  curve K22 (32.5815, 20.3928) -> (30.9804, 20.0525)
  curve K23 (29.4519, 22.1193) -> (30.9804, 20.0525)
  curve K24 (28.4399, 21.7904) -> (28.418, 19.22)
  curve K25 (28.418, 19.22) -> (26.9227, 18.5542)
  curve K26 (24.9978, 20.258) -> (26.9227, 18.5542)
  curve K27 (24.0763, 19.7259) -> (24.5894, 17.2071)
  curve K28 (24.5894, 17.2071) -> (23.2652, 16.2449)
  curve K29 (21.0281, 17.5113) -> (23.2652, 16.2449)
  curve K30 (20.2374, 16.7993) -> (21.2629, 14.4421)
  curve K31 (21.2629, 14.4421) -> (20.1677, 13.2257)
  curve K32 (17.7162, 13.9993) -> (20.1677, 13.2257)
  curve K33 (17.0908, 13.1384) -> (18.584, 11.046)
  curve K34 (18.584, 11.046) -> (17.7656, 9.6284)
  curve K35 (15.2069, 9.8754) -> (17.7656, 9.6284)
  curve K36 (14.7741, 8.9033) -> (16.6698, 7.1671)
  curve K37 (16.6698, 7.1671) -> (16.1639, 5.6104)
  curve K38 (13.6098, 5.32) -> (16.1639, 5.6104)
  curve K39 (13.3886, 4.2792) -> (15.6038, 2.975)
  curve K40 (15.6038, 2.975) -> (15.4327, 1.3471)
  curve K41 (12.9947, 0.5321) -> (15.4327, 1.3471)
  curve K42 (12.9947, -0.5321) -> (15.4327, -1.3471)
  curve K43 (15.4327, -1.3471) -> (15.6038, -2.975)
  curve K44 (13.3886, -4.2792) -> (15.6038, -2.975)
  curve K45 (13.6098, -5.32) -> (16.1639, -5.6104)
  curve K46 (16.1639, -5.6104) -> (16.6698, -7.1671)
  curve K47 (14.7741, -8.9033) -> (16.6698, -7.1671)
  curve K48 (15.2069, -9.8754) -> (17.7656, -9.6284)
  curve K49 (17.7656, -9.6284) -> (18.584, -11.046)
  curve K50 (17.0908, -13.1384) -> (18.584, -11.046)
  curve K51 (17.7162, -13.9993) -> (20.1677, -13.2257)
  curve K52 (20.1677, -13.2257) -> (21.2629, -14.4421)
  curve K53 (20.2374, -16.7993) -> (21.2629, -14.4421)
  curve K54 (21.0281, -17.5113) -> (23.2652, -16.2449)
  curve K55 (23.2652, -16.2449) -> (24.5894, -17.2071)
  curve K56 (24.0763, -19.7259) -> (24.5894, -17.2071)
  curve K57 (24.9978, -20.258) -> (26.9227, -18.5542)
  curve K58 (26.9227, -18.5542) -> (28.418, -19.22)
  curve K59 (28.4399, -21.7904) -> (28.418, -19.22)
  curve K60 (29.4519, -22.1193) -> (30.9804, -20.0525)
  curve K61 (30.9804, -20.0525) -> (32.5815, -20.3928)
  curve K62 (33.1373, -22.9026) -> (32.5815, -20.3928)
  curve K63 (34.1956, -23.0139) -> (35.261, -20.6745)
  curve K64 (35.261, -20.6745) -> (36.8979, -20.6745)
  curve K65 (37.9633, -23.0139) -> (36.8979, -20.6745)
  curve K66 (39.0216, -22.9026) -> (39.5773, -20.3928)
  curve K67 (39.5773, -20.3928) -> (41.1784, -20.0525)
  curve K68 (42.707, -22.1193) -> (41.1784, -20.0525)
  curve K69 (43.719, -21.7904) -> (43.7408, -19.22)
  curve K70 (43.7408, -19.22) -> (45.2362, -18.5542)
  curve K71 (47.161, -20.258) -> (45.2362, -18.5542)
  curve K72 (48.0826, -19.7259) -> (47.5694, -17.2071)
  curve K73 (47.5694, -17.2071) -> (48.8937, -16.2449)
  curve K74 (51.1307, -17.5113) -> (48.8937, -16.2449)
  curve K75 (51.9215, -16.7993) -> (50.8959, -14.4421)
  curve K76 (50.8959, -14.4421) -> (51.9912, -13.2257)
  curve K77 (54.4426, -13.9993) -> (51.9912, -13.2257)
  curve K78 (55.0681, -13.1384) -> (53.5748, -11.046)
  curve K79 (53.5748, -11.046) -> (54.3933, -9.6284)
  curve K80 (56.952, -9.8754) -> (54.3933, -9.6284)
  curve K81 (57.3848, -8.9033) -> (55.4891, -7.1671)
  curve K82 (55.4891, -7.1671) -> (55.9949, -5.6104)
  curve K83 (58.5491, -5.32) -> (55.9949, -5.6104)
  curve K84 (58.7703, -4.2792) -> (56.5551, -2.975)
  curve K85 (56.5551, -2.975) -> (56.7262, -1.3471)
  curve K86 (59.1641, -0.5321) -> (56.7262, -1.3471)
  curve K87 (59.1641, 0.5321) -> (56.7262, 1.3471)
  curve K88 (56.7262, 1.3471) -> (56.5551, 2.975)
  curve K89 (58.7703, 4.2792) -> (56.5551, 2.975)
  curve K90 (58.5491, 5.32) -> (55.9949, 5.6104)
  circle C1 centre (0, 0) radius 2.135
  circle C2 centre (0, 0) radius 17.78
  circle C3 centre (0, 0) radius 20.32
  circle C4 centre (0, 0) radius 15.9385
  arc A1 centre (36.0794, 0) radius 23.0908 clockwise from (56.952, 9.8754) to (57.3848, 8.9033)
  arc A2 centre (36.0794, 0) radius 23.0908 clockwise from (54.4426, 13.9993) to (55.0681, 13.1384)
  arc A3 centre (36.0794, 0) radius 23.0908 clockwise from (51.1307, 17.5113) to (51.9215, 16.7993)
  arc A4 centre (36.0794, 0) radius 23.0908 clockwise from (47.161, 20.258) to (48.0826, 19.7259)
  arc A5 centre (36.0794, 0) radius 23.0908 clockwise from (42.707, 22.1193) to (43.719, 21.7904)
  arc A6 centre (36.0794, 0) radius 23.0908 clockwise from (37.9633, 23.0139) to (39.0216, 22.9026)
  arc A7 centre (36.0794, 0) radius 23.0908 clockwise from (33.1373, 22.9026) to (34.1956, 23.0139)
  arc A8 centre (36.0794, 0) radius 23.0908 clockwise from (28.4399, 21.7904) to (29.4519, 22.1193)
  arc A9 centre (36.0794, 0) radius 23.0908 clockwise from (24.0763, 19.7259) to (24.9978, 20.258)
  arc A10 centre (36.0794, 0) radius 23.0908 clockwise from (20.2374, 16.7993) to (21.0281, 17.5113)
  arc A11 centre (36.0794, 0) radius 23.0908 clockwise from (17.0908, 13.1384) to (17.7162, 13.9993)
  arc A12 centre (36.0794, 0) radius 23.0908 clockwise from (14.7741, 8.9033) to (15.2069, 9.8754)
  arc A13 centre (36.0794, 0) radius 23.0908 clockwise from (13.3886, 4.2792) to (13.6098, 5.32)
  arc A14 centre (36.0794, 0) radius 23.0908 clockwise from (12.9947, -0.5321) to (12.9947, 0.5321)
  arc A15 centre (36.0794, 0) radius 23.0908 clockwise from (13.6098, -5.32) to (13.3886, -4.2792)
  arc A16 centre (36.0794, 0) radius 23.0908 clockwise from (15.2069, -9.8754) to (14.7741, -8.9033)
  arc A17 centre (36.0794, 0) radius 23.0908 clockwise from (17.7162, -13.9993) to (17.0908, -13.1384)
  arc A18 centre (36.0794, 0) radius 23.0908 clockwise from (21.0281, -17.5113) to (20.2374, -16.7993)
  arc A19 centre (36.0794, 0) radius 23.0908 clockwise from (24.9978, -20.258) to (24.0763, -19.7259)
  arc A20 centre (36.0794, 0) radius 23.0908 clockwise from (29.4519, -22.1193) to (28.4399, -21.7904)
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  point P5 (0, 0)
  point P7 (0, 0)
  point P10 (0, 0)
  point P13 (10.4547, 22.4202)
  point P14 (10.4547, -22.4202)
  point P72 (12.9947, -0.5321)
  concentric C1 C2
  tangent L1 C2
  horizontal L3
  coincident P5 P7
  horizontal L5
  coincident P5 P10
  vertical L6
  coincident L4 P13
  coincident L2 P14
  dimension "d272" = 2.54
  dimension "d275" angle L2 L3 = 65 (= "d276")
  dimension "d276" angle L4 L5 = 65
  dimension "d414" distance L6 P72 = 2.54
extrude "Extrude6" cut sketch "Driven Gear Cover -> Drive Cut Out" against normal blind 19.05
component_from_bodies "Body->Comp2"
joint "Assemble2" alignAngle 360 alignOffsetX 0 alignOffsetY 0 alignOffsetZ 0
sketch "Shaft Motor Cylinder 0" plane through (0, 0, 33.02) normal (0, 0, -1) x axis (1, 0, 0)
  line L1 (38.1019, -1.4964) -> (38.1019, 1.4964)
  line L2 (34.057, 1.4964) -> (34.057, -1.4964)
  circle C1 centre (36.0794, 0) radius 5.0559
  arc A1 centre (36.0794, 0) radius 2.4956 clockwise from (38.0797, -1.4922) to (34.0792, -1.4922)
  arc A2 centre (36.0794, 0) radius 2.4955 clockwise from (38.0797, 1.4922) to (38.0797, -1.4922)
  arc A3 centre (36.0794, 0) radius 2.4955 clockwise from (34.0792, 1.4922) to (38.0797, 1.4922)
  arc A4 centre (36.0794, 0) radius 2.4955 clockwise from (34.0792, -1.4922) to (34.0792, 1.4922)
  arc A5 centre (36.0794, 0) radius 2.7495 clockwise from (38.2833, 1.6441) to (38.2833, -1.6441)
  arc A6 centre (36.0794, 0) radius 2.7495 clockwise from (33.8756, 1.6441) to (38.2833, 1.6441)
  arc A7 centre (36.0794, 0) radius 2.7495 clockwise from (33.8756, -1.6441) to (33.8756, 1.6441)
  arc A8 centre (36.0794, 0) radius 2.7495 clockwise from (38.2833, -1.6441) to (33.8756, -1.6441)
  dimension "d285" = 0.254 (= "clearance")
extrude "Extrude2" new body sketch "Shaft Motor Cylinder 0" profile of C1 A8 A7 A6 A5 along normal blind 2.54
combine "Combine2"
chamfer "Chamfer3" distance 0.508 distance 0.1905
position "Position7"
work_plane "WorkPlane1" AlongDistance -88.9 (= "( -7 / 2 ) * 1 in")
sketch "Button & Pot Placement" plane through (-88.9, 0, 0) normal (1, 0, 0) x axis (0, 1, 0)
  line L1 (-88.9, 0) -> (88.9, 0)
  line L2 (-88.9, 60.325) -> (88.9, 60.325)
  line L3 (0, 19.05) -> (0, 0)
  line L4 (-12.7, 19.05) -> (0, 19.05)
  line L5 (12.7, 19.05) -> (0, 19.05)
  line L6 (0, 38.1) -> (0, 19.05)
  point P1 (0, 0)
  point P6 (0, 0)
  point P7 (0, 19.05)
  point P8 (-12.7, 19.05)
  point P10 (0, 38.1)
  coincident P1 P6
  perpendicular L1 L3
  perpendicular L3 L4
  perpendicular L3 L5
  equal L4 L5
  perpendicular L4 L6
  dimension "d293" distance P7 P8 = 12.7
  dimension "d294" distance P6 P7 = 19.05
  dimension "d304" distance P7 P10 = 19.05 (= "( 3 / 4 ) * 1 in")
joint "Assemble12" alignAngle 90 alignOffsetX 0 alignOffsetY 0
joint "Assemble13" alignAngle 90 alignOffsetX 0 alignOffsetY 0
joint "Assemble14" alignAngle 180 alignOffsetX 0 alignOffsetY 0 alignOffsetZ -12.7
sketch "Motor Controller Profile" plane through (0, 0, 60.325) normal (0, 0, -1) x axis (1, 0, 0)
  line L1 (-45.4307, -23.293) -> (-36.9975, -20.2235)
  line L2 (-41.3411, -8.2894) -> (-49.7744, -11.3589)
  line L3 (2.5431, 50.9906) -> (0.9847, 42.1525)
  line L4 (13.4917, 39.9472) -> (15.0501, 48.7853)
  line L5 (42.8876, -27.6977) -> (36.0128, -21.929)
  line L6 (27.8494, -31.6578) -> (34.7242, -37.4264)
  line L7 (-86.36, -16.0401) -> (-36.195, -16.0401)
  line L8 (-36.195, 16.0401) -> (-86.36, 16.0401)
  line L9 (-55.245, -16.0401) -> (-55.245, 16.0401)
  line L10 (-86.36, -16.2941) -> (-36.195, -16.2941)
  line L11 (-36.195, 16.2941) -> (-86.36, 16.2941)
  line L12 (-86.36, 16.2941) -> (-86.36, -16.2941)
  line L13 (-38.7289, 28.933) -> (-35.5184, 26.2391)
  line L14 (-35.2186, 33.1164) -> (-38.7289, 28.933)
  line L15 (-32.0081, 30.4224) -> (-35.2186, 33.1164)
  line L16 (-35.5184, 26.2391) -> (-32.0081, 30.4224)
  line L17 (-11.0703, -47.0584) -> (-5.6923, -48.0067)
  line L18 (-10.3425, -42.9311) -> (-11.0703, -47.0584)
  line L19 (-4.9645, -43.8794) -> (-10.3425, -42.9311)
  line L20 (-5.6923, -48.0067) -> (-4.9645, -43.8794)
  line L21 (44.4212, 19.0737) -> (40.4829, 17.6403)
  line L22 (46.2889, 13.9421) -> (44.4212, 19.0737)
  line L23 (42.3507, 12.5086) -> (46.2889, 13.9421)
  line L24 (40.4829, 17.6403) -> (42.3507, 12.5086)
  arc A1 centre (0, 0) radius 51.054 clockwise from (-45.4307, -23.293) to (-49.7744, -11.3589)
  arc A2 centre (0, 0) radius 42.164 clockwise from (-41.3411, -8.2894) to (0.9847, 42.1525)
  arc A3 centre (0, 0) radius 51.054 clockwise from (2.5431, 50.9906) to (15.0501, 48.7853)
  arc A4 centre (0, 0) radius 42.164 clockwise from (13.4917, 39.9472) to (36.0128, -21.929)
  arc A5 centre (0, 0) radius 51.054 clockwise from (42.8876, -27.6977) to (34.7242, -37.4264)
  arc A6 centre (0, 0) radius 42.164 clockwise from (27.8494, -31.6578) to (-36.9975, -20.2235)
  circle C1 centre (0, 0) radius 85.725
  point P19 (-55.245, 16.0401)
  point P20 (-55.245, -16.0401)
  point P15 (-36.195, -16.0401)
  coincident L8 P19
  coincident L7 P20
  perpendicular L7 L9
  perpendicular L8 L12
  dimension "d309" distance P15 L9 = 19.05
extrude "Extrude1" cut sketch "Motor Controller Profile" profile of A1 A2 C1 L7 L8 L9 L10 L11 L12 along normal blind 31.75
sketch "Motor Controller Rails" plane through (0, 0, 60.325) normal (0, 0, -1) x axis (1, 0, 0)
  line L1 (-86.36, 16.2941) -> (-84.1622, 16.2941)
  line L2 (-86.36, -16.2941) -> (-86.36, 16.2941)
  line L3 (-84.1622, -16.2941) -> (-86.36, -16.2941)
  line L4 (-41.3411, -8.2894) -> (-49.7744, -11.3589)
  line L5 (2.5431, 50.9906) -> (0.9847, 42.1525)
  line L6 (13.4917, 39.9472) -> (15.0501, 48.7853)
  line L7 (42.8876, -27.6977) -> (36.0128, -21.929)
  line L8 (27.8494, -31.6578) -> (34.7242, -37.4264)
  line L9 (-45.4307, -23.293) -> (-36.9975, -20.2235)
  line L10 (-58.7622, 16.2941) -> (-84.1622, 16.2941)
  line L11 (-58.7622, 18.8341) -> (-58.7622, 16.2941)
  line L12 (-84.1622, 18.8341) -> (-58.7622, 18.8341)
  line L13 (-84.1622, 16.2941) -> (-84.1622, 18.8341)
  line L14 (-58.7622, -16.2941) -> (-84.1622, -16.2941)
  line L15 (-58.7622, -18.8341) -> (-58.7622, -16.2941)
  line L16 (-84.1622, -18.8341) -> (-58.7622, -18.8341)
  line L17 (-84.1622, -16.2941) -> (-84.1622, -18.8341)
  line L18 (44.4212, 19.0737) -> (40.4829, 17.6403)
  line L19 (46.2889, 13.9421) -> (44.4212, 19.0737)
  line L20 (42.3507, 12.5086) -> (46.2889, 13.9421)
  line L21 (40.4829, 17.6403) -> (42.3507, 12.5086)
  line L22 (-11.0703, -47.0584) -> (-5.6923, -48.0067)
  line L23 (-10.3425, -42.9311) -> (-11.0703, -47.0584)
  line L24 (-4.9645, -43.8794) -> (-10.3425, -42.9311)
  line L25 (-5.6923, -48.0067) -> (-4.9645, -43.8794)
  line L26 (-38.7289, 28.933) -> (-35.5184, 26.2391)
  line L27 (-35.2186, 33.1164) -> (-38.7289, 28.933)
  line L28 (-32.0081, 30.4224) -> (-35.2186, 33.1164)
  line L29 (-35.5184, 26.2391) -> (-32.0081, 30.4224)
  arc A1 centre (0, 0) radius 85.725 clockwise from (-84.1622, 16.2941) to (-84.1622, -16.2941)
  arc A2 centre (0, 0) radius 51.054 clockwise from (-45.4307, -23.293) to (-49.7744, -11.3589)
  arc A3 centre (0, 0) radius 42.164 clockwise from (-41.3411, -8.2894) to (0.9847, 42.1525)
  arc A4 centre (0, 0) radius 51.054 clockwise from (2.5431, 50.9906) to (15.0501, 48.7853)
  arc A5 centre (0, 0) radius 42.164 clockwise from (13.4917, 39.9472) to (36.0128, -21.929)
  arc A6 centre (0, 0) radius 51.054 clockwise from (42.8876, -27.6977) to (34.7242, -37.4264)
  arc A7 centre (0, 0) radius 42.164 clockwise from (27.8494, -31.6578) to (-36.9975, -20.2235)
  point P3 (-84.1622, 16.2941)
  point P19 (-84.1622, 16.2941)
  point P2 (-84.1622, -16.2941)
  point P23 (-84.1622, -16.2941)
  point P25 (-58.7622, -18.8341)
  point P26 (-84.1622, -18.8341)
  point P24 (-58.7622, -16.2941)
  horizontal L10
  vertical L11
  horizontal L12
  vertical L13
  coincident P3 P19
  horizontal L14
  vertical L15
  horizontal L16
  vertical L17
  coincident P2 P23
  equal L10 L14
  equal L11 L15
  dimension "d314" distance P25 P26 = 25.4
  dimension "d315" distance P24 P25 = 2.54
extrude "Extrude2" add sketch "Motor Controller Rails" profile of A1 L10 L11 L12 L14 L15 L16 along normal blind 13.335
sketch "Motor Controller Foundation" plane through (0, 0, 60.325) normal (0, 0, -1) x axis (1, 0, 0)
  line L1 (-83.6305, -18.8341) -> (-58.7622, -18.8341)
  line L2 (-58.7622, 18.8341) -> (-83.6305, 18.8341)
  line L3 (-58.7622, 16.2941) -> (-58.7622, 18.8341)
  line L4 (-86.36, 16.2941) -> (-58.7622, 16.2941)
  line L5 (-86.36, -16.2941) -> (-86.36, 16.2941)
  line L6 (-58.7622, -16.2941) -> (-86.36, -16.2941)
  line L7 (-58.7622, -18.8341) -> (-58.7622, -16.2941)
  line L8 (-41.3411, -8.2894) -> (-49.7744, -11.3589)
  line L9 (2.5431, 50.9906) -> (0.9847, 42.1525)
  line L10 (13.4917, 39.9472) -> (15.0501, 48.7853)
  line L11 (42.8876, -27.6977) -> (36.0128, -21.929)
  line L12 (27.8494, -31.6578) -> (34.7242, -37.4264)
  line L13 (-45.4307, -23.293) -> (-36.9975, -20.2235)
  line L14 (-58.7622, 16.2941) -> (-86.36, 16.2941)
  line L15 (-58.7622, -16.2941) -> (-58.7622, 16.2941)
  line L16 (-86.36, -16.2941) -> (-58.7622, -16.2941)
  line L17 (-86.36, 16.2941) -> (-86.36, -16.2941)
  line L18 (-38.7289, 28.933) -> (-35.5184, 26.2391)
  line L19 (-35.2186, 33.1164) -> (-38.7289, 28.933)
  line L20 (-32.0081, 30.4224) -> (-35.2186, 33.1164)
  line L21 (-35.5184, 26.2391) -> (-32.0081, 30.4224)
  line L22 (-11.0703, -47.0584) -> (-5.6923, -48.0067)
  line L23 (-10.3425, -42.9311) -> (-11.0703, -47.0584)
  line L24 (-4.9645, -43.8794) -> (-10.3425, -42.9311)
  line L25 (-5.6923, -48.0067) -> (-4.9645, -43.8794)
  line L26 (44.4212, 19.0737) -> (40.4829, 17.6403)
  line L27 (46.2889, 13.9421) -> (44.4212, 19.0737)
  line L28 (42.3507, 12.5086) -> (46.2889, 13.9421)
  line L29 (40.4829, 17.6403) -> (42.3507, 12.5086)
  arc A1 centre (0, 0) radius 85.725 clockwise from (-83.6305, 18.8341) to (-83.6305, -18.8341)
  arc A2 centre (0, 0) radius 51.054 clockwise from (-45.4307, -23.293) to (-49.7744, -11.3589)
  arc A3 centre (0, 0) radius 42.164 clockwise from (-41.3411, -8.2894) to (0.9847, 42.1525)
  arc A4 centre (0, 0) radius 51.054 clockwise from (2.5431, 50.9906) to (15.0501, 48.7853)
  arc A5 centre (0, 0) radius 42.164 clockwise from (13.4917, 39.9472) to (36.0128, -21.929)
  arc A6 centre (0, 0) radius 51.054 clockwise from (42.8876, -27.6977) to (34.7242, -37.4264)
  arc A7 centre (0, 0) radius 42.164 clockwise from (27.8494, -31.6578) to (-36.9975, -20.2235)
  point P10 (-58.7622, -16.2941)
  point P25 (-58.7622, -16.2941)
  point P8 (-86.36, 16.2941)
  point P23 (-86.36, 16.2941)
  horizontal L14
  vertical L15
  horizontal L16
  vertical L17
  coincident P10 P25
  coincident P8 P23
extrude "Extrude3" add sketch "Motor Controller Foundation" profile of L4 L5 L6 L14 L15 L16 L17 along normal blind 8.8773 (= "0.462 in - 0.1125 in")
chamfer "Chamfer3" distance 0.635
sketch "Pot Hole" plane through (-88.9, 0, 0) normal (1, 0, 0) x axis (0, 1, 0)
  circle C1 centre (0, 38.1) radius 3.3655
  circle C2 centre (0, 38.1) radius 3.3655
  circle C3 centre (0, 38.1) radius 3.6195
  dimension "d320" = 0.254 (= "clearance")
extrude "Extrude4" cut sketch "Pot Hole" along normal blind 17.78
sketch "Button Hole" plane through (-88.9, 0, 0) normal (1, 0, 0) x axis (0, 1, 0)
  circle C1 centre (-12.7, 19.05) radius 6.096
  circle C2 centre (-12.7, 19.05) radius 6.096
  circle C3 centre (12.7, 19.05) radius 6.096
  circle C4 centre (12.7, 19.05) radius 6.096
  circle C5 centre (12.7, 19.05) radius 6.604
  circle C6 centre (-12.7, 19.05) radius 6.604
  circle C7 centre (12.7, 19.05) radius 8.128
  circle C8 centre (-12.7, 19.05) radius 8.128
  dimension "d323" = 0.508 (= "clearance + 0.01 in")
  dimension "d324" = 0.508 (= "clearance + 0.01 in")
  dimension "d325" = 2.032 (= "clearance + 0.02 in + 0.05 in")
  dimension "d326" = 2.032 (= "clearance + 0.02 in + 0.05 in")
extrude "Extrude5" add sketch "Button Hole" + "Profile" profile of S1:C5 S1:C6 S1:C7 S1:C8 blind -0.127 second side blind -6.35
component_insert "Component Insert7"
position "Position8"
position "Position9"
joint "Assemble15" alignAngle 10 alignOffsetX 0 alignOffsetY 0 alignOffsetZ 0
position "Position10"
sketch "Controlls Thru Holes" plane through (-87.6745, 15.4594, 0) normal (-0.9848, 0.1736, 0) x axis (-0.1736, -0.9848, 0)
  curve K1 (0, 34.4805) -> (0, 41.7195)
  curve K2 (0, 41.7195) -> (0, 34.4805)
  curve K3 (0, 34.2265) -> (0, 41.9735)
  curve K4 (0, 41.9735) -> (0, 34.2265)
  circle C1 centre (-12.7, 19.05) radius 6.604
  circle C2 centre (-12.7, 19.05) radius 8.128
  circle C3 centre (12.7, 19.05) radius 6.604
extrude "Extrude6" cut sketch "Controlls Thru Holes" profile of C1 C3 K1 K2 K4 K3 along a picked direction blind -10.16
sketch "1st LED Placement" plane through (0, 0, 63.5) normal (0, 0, 1) x axis (-1, 0, 0)
  line L1 (-85.725, 0) -> (0, 0)
  circle C1 centre (0, 0) radius 42.164
  circle C2 centre (0, 0) radius 85.725
  point P2 (0, 0)
  point P3 (0, 0)
  point P4 (-85.725, 0)
  coincident P2 P3
  coincident C2 P4
  horizontal L1
component_insert "Component Insert9"
position "Position12"
sketch "LED Circular Pattern" plane through (0, 0, 63.5) normal (0, 0, 1) x axis (1, 0, 0)
  circle C1 centre (80.01, 0) radius 3.5941
  circle C2 centre (80.01, 0) radius 3.6788
  circle C3 centre (0, 0) radius 88.9
  circle C4 centre (49.8854, 62.5543) radius 3.6788
  circle C5 centre (-17.8039, 78.004) radius 3.6788
  circle C6 centre (-72.0865, 34.715) radius 3.6788
  circle C7 centre (-72.0865, -34.715) radius 3.6788
  circle C8 centre (-17.8039, -78.004) radius 3.6788
  circle C9 centre (49.8854, -62.5543) radius 3.6788
  dimension "d338" = 0.0847 (= "clearance / 3")
  dimension "d340" C-Pattern1-Angle = 360
copy_paste "CutPaste7"
extrude "Extrude7" cut sketch "LED Circular Pattern" profile of C2 C4 C5 C6 C7 C8 C9 against normal blind 17.78
joint "Assemble16" alignAngle 0 alignOffsetX 0 alignOffsetY 0 alignOffsetZ 0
